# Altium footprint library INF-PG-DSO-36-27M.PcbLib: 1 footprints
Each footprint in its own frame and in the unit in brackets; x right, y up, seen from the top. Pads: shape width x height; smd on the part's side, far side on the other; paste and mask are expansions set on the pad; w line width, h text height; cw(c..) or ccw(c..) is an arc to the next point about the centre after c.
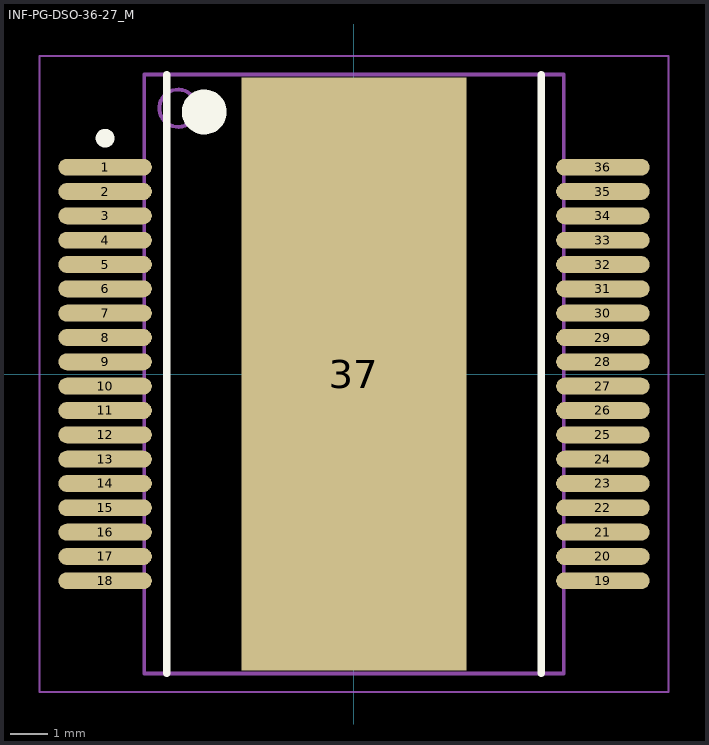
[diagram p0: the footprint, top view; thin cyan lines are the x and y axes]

## INF-PG-DSO-36-27_M [mm] "SOP, 36-Leads, Body 15.9x11mm, Pitch 0.65mm, Thermal Pad 15.84x6mm, IPC Low Density"
height 3.5
pads (37):
  oval 2.5x0.45 smd: 1(-6.65,5.525) 2(-6.65,4.875) 3(-6.65,4.225) 4(-6.65,3.575) 5(-6.65,2.925) 6(-6.65,2.275) 7(-6.65,1.625) 8(-6.65,0.975) 9(-6.65,0.325) 10(-6.65,-0.325) 11(-6.65,-0.975) 12(-6.65,-1.625) 13(-6.65,-2.275) 14(-6.65,-2.925) 15(-6.65,-3.575) 16(-6.65,-4.225) 17(-6.65,-4.875) 18(-6.65,-5.525) 19(6.65,-5.525) 20(6.65,-4.875) 21(6.65,-4.225) 22(6.65,-3.575) 23(6.65,-2.925) 24(6.65,-2.275) 25(6.65,-1.625) 26(6.65,-0.975) 27(6.65,-0.325) 28(6.65,0.325) 29(6.65,0.975) 30(6.65,1.625) 31(6.65,2.275) 32(6.65,2.925) 33(6.65,3.575) 34(6.65,4.225) 35(6.65,4.875) 36(6.65,5.525)
  rect 6x15.84 smd: 37(0,0)
Top Overlay:
  circle w0.25: c-6.65,6.3 r0.125
  circle w0.6: c-4,7 r0.3
  lines w0.2: -5,-8 -5,8 ; 5,-8 5,8
Mechanical 13:
  circle w0.1: c-4.7,7.1 r0.5
  lines w0.1: -5.6,-8 -5.6,8 5.6,8 5.6,-8 -5.6,-8
Mechanical 15:
  lines w0.05: -8.4,-8.5 -8.4,8.5 8.4,8.5 8.4,-8.5 -8.4,-8.5
  lines w0.1: -0.5,0 0.5,0 ; 0,-0.5 0,0.5
3D body: height 3.5, standoff 0, extent -5.6,-8 5.6,8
